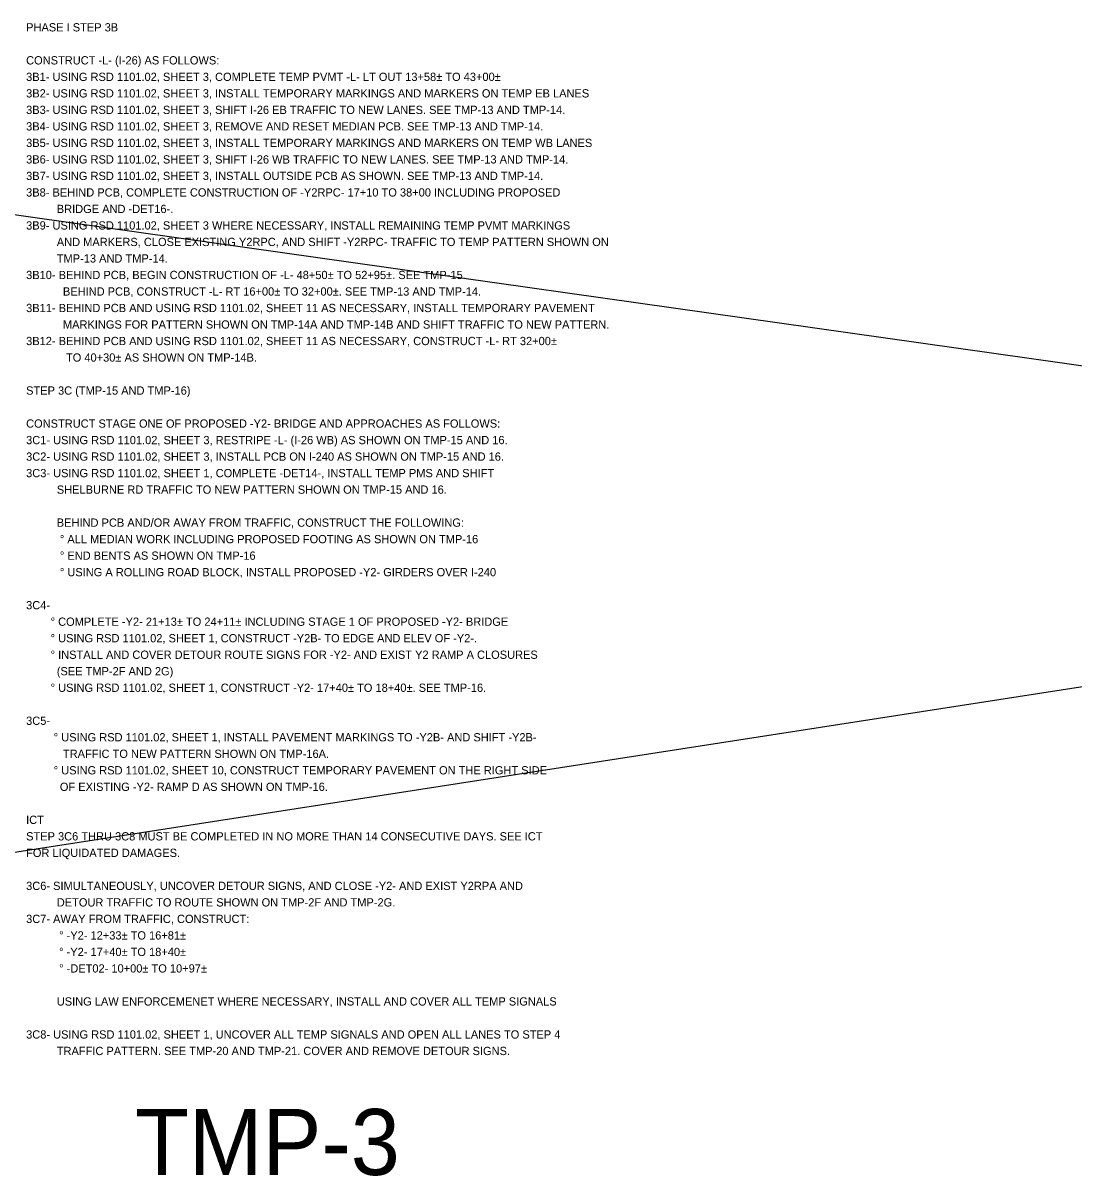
# Model space of a CAD drawing. Extents: x 2483905 to 2494512, y 366160 to 372330.
# Drawn here: x 2488014 to 2488905, y 371326 to 372304 of the extents above; entities that cross this region are included whole.
import ezdxf

# ---------------------------------------------------------------- set-up
doc = ezdxf.new("R2010")
doc.units = 0
doc.layers.add('TC SHEET BORDER LINE THIN', color=7, linetype='Continuous')
doc.layers.add('TC SHEET LAYOUT SHAPE', color=7, linetype='Continuous')

msp = doc.modelspace()

# ---------------------------------------------------------------- linework, layer by layer
at = {"layer": 'TC SHEET BORDER LINE THIN'}
for p, q in [((2486912.05, 372296.36), (2492000.77, 371576.98)), ((2486863.19, 371423.32), (2492035.67, 372226.52))]:
    msp.add_line(p, q, dxfattribs=at)

# ---------------------------------------------------------------- texts
for s, p in [('PHASE I STEP 3B', (2488016.91, 372296.91)), ('CONSTRUCT -L- (I-26) AS FOLLOWS:', (2488016.91, 372268.91)), ('3B1- USING RSD 1101.02, SHEET 3, COMPLETE TEMP PVMT -L- LT OUT 13+58± TO 43+00±', (2488016.91, 372254.91)), ('3B2- USING RSD 1101.02, SHEET 3, INSTALL TEMPORARY MARKINGS AND MARKERS ON TEMP EB LANES', (2488016.91, 372240.91)), ('3B3- USING RSD 1101.02, SHEET 3, SHIFT I-26 EB TRAFFIC TO NEW LANES. SEE TMP-13 AND TMP-14.', (2488016.91, 372226.91)), ('3B4- USING RSD 1101.02, SHEET 3, REMOVE AND RESET MEDIAN PCB. SEE TMP-13 AND TMP-14.', (2488016.91, 372212.91)), ('3B5- USING RSD 1101.02, SHEET 3, INSTALL TEMPORARY MARKINGS AND MARKERS ON TEMP WB LANES', (2488016.91, 372198.91)), ('3B6- USING RSD 1101.02, SHEET 3, SHIFT I-26 WB TRAFFIC TO NEW LANES. SEE TMP-13 AND TMP-14.', (2488016.91, 372184.91)), ('3B7- USING RSD 1101.02, SHEET 3, INSTALL OUTSIDE PCB AS SHOWN. SEE TMP-13 AND TMP-14.', (2488016.91, 372170.91)), ('3B8- BEHIND PCB, COMPLETE CONSTRUCTION OF -Y2RPC- 17+10 TO 38+00 INCLUDING PROPOSED', (2488016.91, 372156.91)), ('          BRIDGE AND -DET16-.', (2488016.91, 372142.91)), ('3B9- USING RSD 1101.02, SHEET 3 WHERE NECESSARY, INSTALL REMAINING TEMP PVMT MARKINGS', (2488016.91, 372128.91)), ('          AND MARKERS, CLOSE EXISTING Y2RPC, AND SHIFT -Y2RPC- TRAFFIC TO TEMP PATTERN SHOWN ON', (2488016.91, 372114.91)), ('          TMP-13 AND TMP-14.', (2488016.91, 372100.91)), ('3B10- BEHIND PCB, BEGIN CONSTRUCTION OF -L- 48+50± TO 52+95±. SEE TMP-15.', (2488016.91, 372086.91)), ('            BEHIND PCB, CONSTRUCT -L- RT 16+00± TO 32+00±. SEE TMP-13 AND TMP-14.', (2488016.91, 372072.91)), ('3B11- BEHIND PCB AND USING RSD 1101.02, SHEET 11 AS NECESSARY, INSTALL TEMPORARY PAVEMENT', (2488016.91, 372058.91)), ('            MARKINGS FOR PATTERN SHOWN ON TMP-14A AND TMP-14B AND SHIFT TRAFFIC TO NEW PATTERN.', (2488016.91, 372044.91)), ('3B12- BEHIND PCB AND USING RSD 1101.02, SHEET 11 AS NECESSARY, CONSTRUCT -L- RT 32+00± ', (2488016.91, 372030.91)), ('             TO 40+30± AS SHOWN ON TMP-14B.', (2488016.91, 372016.91)), ('STEP 3C (TMP-15 AND TMP-16)', (2488016.91, 371988.91)), ('CONSTRUCT STAGE ONE OF PROPOSED -Y2- BRIDGE AND APPROACHES AS FOLLOWS:', (2488016.91, 371960.91)), ('3C1- USING RSD 1101.02, SHEET 3, RESTRIPE -L- (I-26 WB) AS SHOWN ON TMP-15 AND 16.', (2488016.91, 371946.91)), ('3C2- USING RSD 1101.02, SHEET 3, INSTALL PCB ON I-240 AS SHOWN ON TMP-15 AND 16.', (2488016.91, 371932.91)), ('3C3- USING RSD 1101.02, SHEET 1, COMPLETE -DET14-, INSTALL TEMP PMS AND SHIFT', (2488016.91, 371918.91)), ('          SHELBURNE RD TRAFFIC TO NEW PATTERN SHOWN ON TMP-15 AND 16.', (2488016.91, 371904.91)), ('          BEHIND PCB AND/OR AWAY FROM TRAFFIC, CONSTRUCT THE FOLLOWING:', (2488016.91, 371876.91)), ('           ° ALL MEDIAN WORK INCLUDING PROPOSED FOOTING AS SHOWN ON TMP-16', (2488016.91, 371862.91)), ('           ° END BENTS AS SHOWN ON TMP-16', (2488016.91, 371848.91)), ('           ° USING A ROLLING ROAD BLOCK, INSTALL PROPOSED -Y2- GIRDERS OVER I-240', (2488016.91, 371834.91)), ('3C4- ', (2488016.91, 371806.91)), ('        ° COMPLETE -Y2- 21+13± TO 24+11± INCLUDING STAGE 1 OF PROPOSED -Y2- BRIDGE', (2488016.91, 371792.91)), ('        ° USING RSD 1101.02, SHEET 1, CONSTRUCT -Y2B- TO EDGE AND ELEV OF -Y2-.', (2488016.91, 371778.91)), ('        ° INSTALL AND COVER DETOUR ROUTE SIGNS FOR -Y2- AND EXIST Y2 RAMP A CLOSURES', (2488016.91, 371764.91)), ('          (SEE TMP-2F AND 2G)', (2488016.91, 371750.91)), ('        ° USING RSD 1101.02, SHEET 1, CONSTRUCT -Y2- 17+40± TO 18+40±. SEE TMP-16.', (2488016.91, 371736.91)), ('3C5- ', (2488016.91, 371708.91)), ('         ° USING RSD 1101.02, SHEET 1, INSTALL PAVEMENT MARKINGS TO -Y2B- AND SHIFT -Y2B-', (2488016.91, 371694.91)), ('            TRAFFIC TO NEW PATTERN SHOWN ON TMP-16A.', (2488016.91, 371680.91)), ('         ° USING RSD 1101.02, SHEET 10, CONSTRUCT TEMPORARY PAVEMENT ON THE RIGHT SIDE', (2488016.91, 371666.91)), ('           OF EXISTING -Y2- RAMP D AS SHOWN ON TMP-16.', (2488016.91, 371652.91)), ('ICT', (2488016.91, 371624.91)), ('STEP 3C6 THRU 3C8 MUST BE COMPLETED IN NO MORE THAN 14 CONSECUTIVE DAYS. SEE ICT', (2488016.91, 371610.91)), ('FOR LIQUIDATED DAMAGES.', (2488016.91, 371596.91)), ('3C6- SIMULTANEOUSLY, UNCOVER DETOUR SIGNS, AND CLOSE -Y2- AND EXIST Y2RPA AND', (2488016.91, 371568.91)), ('          DETOUR TRAFFIC TO ROUTE SHOWN ON TMP-2F AND TMP-2G.', (2488016.91, 371554.91)), ('3C7- AWAY FROM TRAFFIC, CONSTRUCT:', (2488016.91, 371540.91)), ('° -Y2- 12+33± TO 16+81±', (2488044.91, 371526.91)), ('° -Y2- 17+40± TO 18+40±', (2488044.91, 371512.91)), ('° -DET02- 10+00± TO 10+97±', (2488044.91, 371498.91)), ('          USING LAW ENFORCEMENET WHERE NECESSARY, INSTALL AND COVER ALL TEMP SIGNALS', (2488016.91, 371470.91)), ('3C8- USING RSD 1101.02, SHEET 1, UNCOVER ALL TEMP SIGNALS AND OPEN ALL LANES TO STEP 4', (2488016.91, 371442.91)), ('          TRAFFIC PATTERN. SEE TMP-20 AND TMP-21. COVER AND REMOVE DETOUR SIGNS.', (2488016.91, 371428.91))]:
    msp.add_text(s, height=7, dxfattribs=at).set_placement(p)
at = {"layer": 'TC SHEET LAYOUT SHAPE'}
msp.add_text('TMP-3', height=55.996, rotation=0.00008, dxfattribs=at).set_placement((2488109.23, 371327.23))

doc.saveas('drawing.dxf')
